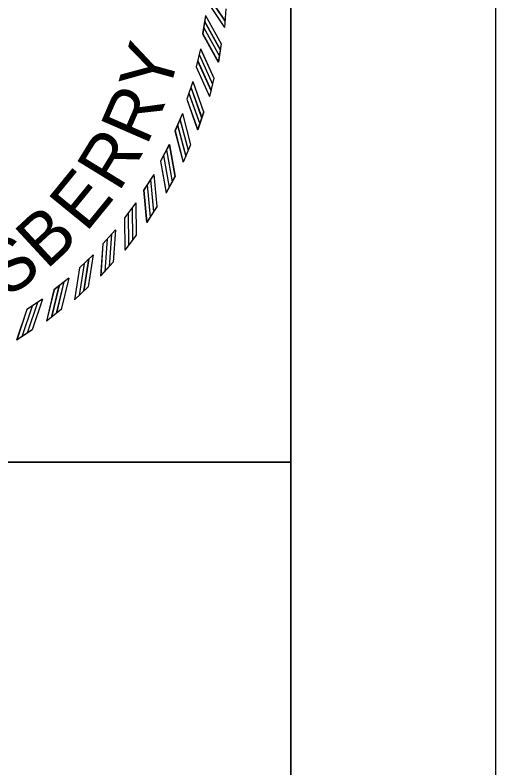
# Model space of a CAD drawing. Extents: x 0 to 1228740, y 0 to 152440.
# Drawn here: x 32.648 to 34, y 16.545 to 18.662 of the extents above; entities that cross this region are included whole.
import ezdxf

# ---------------------------------------------------------------- set-up
doc = ezdxf.new("R2010")
doc.units = 0
for name, color, linetype in [('R_Border', 7, 'Continuous'), ('R_No Plot', 7, 'Continuous'), ('R_Sheet Text', 7, 'Continuous'), ('STAMP', 7, 'Continuous')]:
    doc.layers.add(name, color=color, linetype=linetype)

msp = doc.modelspace()

# ---------------------------------------------------------------- linework, layer by layer
at = {"layer": 'R_Border'}
msp.add_line((33.4231, 0.5768), (33.4231, 21.4232), dxfattribs=at)
msp.add_lwpolyline([(33.9999, 22), (0, 22), (0, 0), (33.9999, 0)], close=True, dxfattribs=at)
at = {"layer": 'R_No Plot'}
for points in [[(33.4231, 17.4052), (33.4231, 10.8708), (1.516, 10.8708), (1.516, 21.4232), (25.1971, 21.4232), (25.1971, 20.4352), (28.7491, 20.4352), (28.7491, 20.0782), (29.1131, 20.0782), (29.1131, 20.1432), (30.6665, 20.1432)], [(33.4231, 17.4052), (33.4231, 0.5768), (1.516, 0.5768), (1.516, 21.4232), (25.1971, 21.4232), (25.1971, 20.4352), (28.7491, 20.4352), (28.7491, 20.0782), (29.1131, 20.0782), (29.1131, 20.1432), (30.6665, 20.1432)], [(30.6665, 20.1432), (30.6665, 17.4052), (33.4231, 17.4052)], [(30.6665, 20.1432), (30.6665, 17.4052), (33.4231, 17.4052)]]:
    msp.add_lwpolyline(points, dxfattribs=at)
for points in [[(1.516, 21.4232), (33.4231, 21.4232), (33.4231, 0.5768), (1.516, 0.5768)], [(30.6665, 20.1618), (33.4231, 20.1618), (33.4231, 17.4052), (30.6665, 17.4052)]]:
    msp.add_lwpolyline(points, close=True, dxfattribs=at)
at = {"layer": 'R_Sheet Text'}
for p, q in [((33.2403, 18.6796), (33.2364, 18.6271)), ((33.1833, 18.6609), (33.1751, 18.6087)), ((33.1692, 18.5672), (33.1567, 18.516)), ((33.2275, 18.5812), (33.2193, 18.5292)), ((33.2066, 18.4842), (33.1942, 18.4331)), ((33.1474, 18.4751), (33.1308, 18.4251)), ((33.1181, 18.3851), (33.0973, 18.3366)), ((33.1779, 18.3893), (33.1612, 18.3394)), ((33.0814, 18.2979), (33.0567, 18.2512)), ((33.1413, 18.2971), (33.1206, 18.2487)), ((33.0377, 18.2139), (33.0092, 18.1695)), ((33.0973, 18.2082), (33.0727, 18.1617)), ((32.9871, 18.1339), (32.9551, 18.0919)), ((33.0461, 18.1232), (33.0177, 18.0789)), ((32.9302, 18.0583), (32.8948, 18.0191)), ((32.988, 18.0428), (32.9561, 18.001)), ((32.8671, 17.9876), (32.8287, 17.9515)), ((32.9235, 17.9674), (32.8883, 17.9284)), ((32.7985, 17.9224), (32.7572, 17.8897)), ((32.8531, 17.8977), (32.8147, 17.8617)), ((32.7247, 17.8631), (32.6808, 17.8339)), ((32.777, 17.8339), (32.7358, 17.8012)), ((32.696, 17.7767), (32.6522, 17.7475))]:
    msp.add_line(p, q, dxfattribs=at)
for points in [[(33.1873, 18.7202), (33.2379, 18.6445)], [(33.1859, 18.7028), (33.2364, 18.627)], [(33.1833, 18.6609), (33.2275, 18.5813)], [(33.1781, 18.6261), (33.2222, 18.5465)], [(33.1805, 18.6442), (33.2247, 18.5646)], [(33.1752, 18.6088), (33.2193, 18.5292)], [(33.1692, 18.5673), (33.2066, 18.4843)], [(33.165, 18.5509), (33.2025, 18.4679)], [(33.1611, 18.533), (33.1985, 18.45)], [(33.1568, 18.5161), (33.1942, 18.433)], [(33.1419, 18.4592), (33.1723, 18.3734)], [(33.1474, 18.4752), (33.1778, 18.3894)], [(33.1365, 18.4417), (33.1669, 18.3559)], [(33.1308, 18.4251), (33.1612, 18.3393)], [(33.1181, 18.3852), (33.1413, 18.2972)], [(33.1044, 18.3527), (33.1277, 18.2647)], [(33.1113, 18.3697), (33.1345, 18.2817)], [(33.0974, 18.3367), (33.1206, 18.2486)], [(33.0814, 18.2979), (33.0973, 18.2083)], [(33.0651, 18.2667), (33.081, 18.177)], [(33.0733, 18.283), (33.0892, 18.1934)], [(33.0568, 18.2513), (33.0727, 18.1616)], [(33.0376, 18.214), (33.0461, 18.1233)], [(33.0189, 18.1842), (33.0273, 18.0935)], [(33.0284, 18.1998), (33.0368, 18.1091)], [(33.0093, 18.1695), (33.0177, 18.0789)], [(32.9767, 18.1206), (32.9776, 18.0295)], [(32.9871, 18.1339), (32.988, 18.0429)], [(32.9659, 18.1058), (32.9669, 18.0148)], [(32.9552, 18.092), (32.9561, 18.0009)], [(32.9302, 18.0583), (32.9236, 17.9675)], [(32.9187, 18.0459), (32.9121, 17.9551)], [(32.8949, 18.0191), (32.8883, 17.9283)], [(32.9067, 18.032), (32.9001, 17.9412)], [(32.8547, 17.9762), (32.8406, 17.8863)], [(32.8671, 17.9877), (32.8531, 17.8977)], [(32.8287, 17.9516), (32.8147, 17.8616)], [(32.8416, 17.9634), (32.8276, 17.8735)], [(32.7851, 17.9121), (32.7637, 17.8236)], [(32.7985, 17.9225), (32.7771, 17.834)], [(32.7572, 17.8897), (32.7358, 17.8012)], [(32.7711, 17.9004), (32.7496, 17.8119)], [(32.6956, 17.8435), (32.6669, 17.757)], [(32.7106, 17.8539), (32.6819, 17.7675)], [(32.7247, 17.8632), (32.696, 17.7768)], [(32.6809, 17.8339), (32.6522, 17.7475)]]:
    msp.add_lwpolyline(points, dxfattribs=at)
at = {"layer": 'STAMP'}
for p, q in [((33.2405, 18.6797), (33.2366, 18.6272)), ((33.1835, 18.661), (33.1753, 18.6089)), ((33.1694, 18.5674), (33.1569, 18.5161)), ((33.2277, 18.5813), (33.2195, 18.5294)), ((33.2068, 18.4844), (33.1944, 18.4332)), ((33.1476, 18.4753), (33.1309, 18.4252)), ((33.1183, 18.3853), (33.0975, 18.3368)), ((33.1781, 18.3894), (33.1614, 18.3395)), ((33.0816, 18.298), (33.0569, 18.2514)), ((33.1415, 18.2972), (33.1208, 18.2488)), ((33.0379, 18.214), (33.0094, 18.1696)), ((33.0975, 18.2083), (33.0729, 18.1618)), ((32.9873, 18.134), (32.9553, 18.0921)), ((33.0463, 18.1234), (33.0179, 18.079)), ((32.9303, 18.0584), (32.895, 18.0192)), ((32.9882, 18.0429), (32.9563, 18.0011)), ((32.8673, 17.9877), (32.8288, 17.9517)), ((32.9237, 17.9676), (32.8885, 17.9285)), ((32.7987, 17.9225), (32.7574, 17.8898)), ((32.8532, 17.8978), (32.8149, 17.8618)), ((32.7249, 17.8632), (32.681, 17.834)), ((32.7772, 17.834), (32.736, 17.8013)), ((32.6962, 17.7768), (32.6524, 17.7476))]:
    msp.add_line(p, q, dxfattribs=at)
for points in [[(33.1875, 18.7204), (33.2381, 18.6447)], [(33.1861, 18.7029), (33.2366, 18.6272)], [(33.1835, 18.6611), (33.2277, 18.5814)], [(33.1783, 18.6262), (33.2224, 18.5466)], [(33.1807, 18.6444), (33.2249, 18.5647)], [(33.1754, 18.6089), (33.2195, 18.5293)], [(33.1694, 18.5675), (33.2068, 18.4845)], [(33.1652, 18.551), (33.2027, 18.468)], [(33.1613, 18.5332), (33.1987, 18.4502)], [(33.157, 18.5162), (33.1944, 18.4332)], [(33.1421, 18.4593), (33.1725, 18.3735)], [(33.1476, 18.4753), (33.178, 18.3895)], [(33.1367, 18.4419), (33.1671, 18.356)], [(33.131, 18.4253), (33.1614, 18.3395)], [(33.1183, 18.3853), (33.1415, 18.2973)], [(33.1046, 18.3529), (33.1279, 18.2648)], [(33.1115, 18.3698), (33.1347, 18.2818)], [(33.0976, 18.3368), (33.1208, 18.2488)], [(33.0816, 18.2981), (33.0975, 18.2084)], [(33.0653, 18.2668), (33.0812, 18.1772)], [(33.0735, 18.2832), (33.0894, 18.1935)], [(33.057, 18.2514), (33.0729, 18.1617)], [(33.0378, 18.2141), (33.0463, 18.1235)], [(33.0191, 18.1843), (33.0275, 18.0937)], [(33.0286, 18.1999), (33.037, 18.1093)], [(33.0095, 18.1696), (33.0179, 18.079)], [(32.9769, 18.1207), (32.9778, 18.0296)], [(32.9873, 18.1341), (32.9882, 18.043)], [(32.9661, 18.1059), (32.9671, 18.0149)], [(32.9554, 18.0921), (32.9563, 18.001)], [(32.9303, 18.0585), (32.9238, 17.9676)], [(32.9189, 18.046), (32.9123, 17.9552)], [(32.895, 18.0193), (32.8885, 17.9285)], [(32.9069, 18.0322), (32.9003, 17.9413)], [(32.8549, 17.9763), (32.8408, 17.8864)], [(32.8673, 17.9878), (32.8533, 17.8979)], [(32.8289, 17.9517), (32.8148, 17.8617)], [(32.8418, 17.9635), (32.8277, 17.8736)], [(32.7853, 17.9122), (32.7639, 17.8237)], [(32.7987, 17.9226), (32.7772, 17.8341)], [(32.7574, 17.8898), (32.736, 17.8013)], [(32.7713, 17.9005), (32.7498, 17.8121)], [(32.6957, 17.8436), (32.6671, 17.7572)], [(32.7107, 17.8541), (32.682, 17.7676)], [(32.7249, 17.8633), (32.6962, 17.7769)], [(32.6811, 17.834), (32.6524, 17.7476)]]:
    msp.add_lwpolyline(points, dxfattribs=at)

# ---------------------------------------------------------------- texts
at = {"layer": 'R_Sheet Text'}
for s, rotation, p in [('Y', 74.5264, (33.0777, 18.4323)), ('R', 66.5008, (33.0178, 18.2921)), ('R', 58.4752, (32.9389, 18.1616)), ('E', 50.8144, (32.8473, 18.0484)), ('B', 42.7888, (32.736, 17.9441)), ('S', 35.4928, (32.6231, 17.8636))]:
    msp.add_text(s, height=0.1454, rotation=rotation, dxfattribs=at).set_placement(p)
at = {"layer": 'STAMP'}
for s, rotation, p in [('Y', 74.5264, (33.0779, 18.4325)), ('R', 66.5008, (33.018, 18.2922)), ('R', 58.4752, (32.9391, 18.1617)), ('E', 50.8144, (32.8474, 18.0486)), ('B', 42.7888, (32.7362, 17.9442)), ('S', 35.4928, (32.6233, 17.8637))]:
    msp.add_text(s, height=0.1454, rotation=rotation, dxfattribs=at).set_placement(p)

doc.saveas('drawing.dxf')
